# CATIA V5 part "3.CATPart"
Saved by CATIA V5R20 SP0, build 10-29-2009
Part number: 3
Bounding box of the stored display mesh (mm): x -65 to 65, y 0 to 180, z -0.347 to 44.383
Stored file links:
  E:\Ehsan\Amoozesh\CATIA\CATIA Course\Advanced\Videos\Session-18\3.CATPart
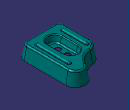
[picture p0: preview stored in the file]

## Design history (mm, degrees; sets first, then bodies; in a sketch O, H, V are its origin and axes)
Set1
  Sweep1: type Segment, GuideCrv Sketch7, GuideSurf xy-plane, Length1 40, Length2 0, Angle 80
  Boundary1: Boundary edge of Sweep1
  Fill1: Boundary Boundary1
  Sketch1 on Fill1, origin (0, 0, 39.3923), H (1, 0, 0), V (0, 1, 0)
    construction line L1 (0, 50) -> (0, 100)
    point P1 (0, 50)
    line L2 (-22.5, 50) -> (-22.5, 100)
    line L3 (22.5, 100) -> (22.5, 50)
    arc A1 centre (0, 100) radius 22.5 from (-22.5, 100) to (22.5, 100) cw
    arc A2 centre (0, 50) radius 22.5 from (22.5, 50) to (-22.5, 50) cw
    distance L1 L2 = 22.5
    length L1 = 50
    distance P1 H = 50
    coincidence: P1 V
    vertical: L1 V
    tangency: A1 L2, A2 L2, A1 L3, A2 L3
  Sweep2: type Segment, GuideCrv Sketch1, GuideSurf xy-plane, Length1 20, Length2 0, Angle 72.5
  Boundary2: Boundary edge of Sweep2
  Fill2: Boundary Boundary2
  Split1: ToCut Fill1, Cutting Sketch1
  Sketch2 on Fill2, origin (0, 0, 20.318), H (1, 0, 0), V (0, 1, 0)
    circle A1 centre (0, 90) radius 8
    point P1 (0, 90)
    circle A2 centre (0, 60) radius 8
    point P2 (0, 60)
    reference projected line E1 (22.5, 50) -> (16.4859, 50) from edge [face of Sweep2 | face of Sweep2]
    radius A1 = 8
    radius A2 = 8
    distance P2 P1 = 30
    distance P2 E1 = 10
    coincidence: P1 V, P2 V
  Split2: ToCut Fill2, Cutting Sketch2
  Plane1: type Offset, RefPlane zx-plane, Offset 35
  Sketch3 on Plane1, origin (0, 35, 0), H (-1, 0, 0), V (0, 0, 1)
    arc A1 centre (40, 39.3923) radius 5 from (45, 39.3923) to (35, 39.3923) ccw
    point P1 (40, 39.3923)
    reference projected line E1 (45, 39.3923) -> (-45, 39.3923) from edge of Sweep1
    construction line L1 (45, 39.3923) -> (35, 39.3923)
    point P2 (45, 39.3923)
    point P3 (35, 39.3923)
    point P4 (-35, 39.3923)
    point P5 (-45, 39.3923)
    arc A2 centre (-40, 39.3923) radius 5 from (-45, 39.3923) to (-35, 39.3923) cw
    construction line L2 (-45, 39.3923) -> (-35, 39.3923)
    point P7 (-45, 39.3923)
    axis line L3 (35, 39.3923) -> (45, 39.3923)
    radius A1 = 5
    distance P1 V = 40
    coincidence: P1 E1, P7 A2
    horizontal: L1 H, L2 H, L3 H
    symmetry: P3 P4 V, P2 P5 V, A1 A2 V
  Extrude1: Lim1 75, Lim2 0, Element1 Sketch3
  Extrude2: Lim1 100, Lim2 0, Direction edge of Fill1, Element1 sketch element
  Revol1: Element1 Sketch3, Angle1 0
  Line1: type PtPt, FirstPoint vertex of Sketch3, SecondPoint vertex of Sketch3
  Revol2: Element1 sketch element, Angle1 90, Line Line1
  Plane2: type Offset, RefPlane Plane1, Offset 100
  Sketch4 on Plane2, origin (0, 135, 0), H (-1, 0, 0), V (0, 0, 1)
    projected arc E1 centre (-40, 39.3923) radius 5 from (-35, 39.3923) to (-45, 39.3923) ccw from sketch element
    axis line L1 (-45, 39.3923) -> (-35, 39.3923)
    horizontal: L1 H
  Revol3: Element1 Sketch4, Angle1 90
  Plane3: type Offset, RefPlane Plane1, Offset 75
  Sketch5 on Plane3, origin (0, 110, 0), H (-1, 0, 0), V (0, 0, 1)
    projected arc E1 centre (40, 39.3923) radius 5 from (45, 39.3923) to (35, 39.3923) ccw from Sketch3.A1
    axis line L1 (35, 39.3923) -> (45, 39.3923)
    horizontal: L1 H
  Revol4: Element1 Sketch5, Angle1 90
  Sketch6 on Split1, origin (0, 0, 39.3923), H (1, 0, 0), V (0, 1, 0)
    projected line E1 (-45, 110) -> (-45, 35) from edge of Extrude1
    projected arc E2 centre (-40, 110) radius 5 from (-35, 110) to (-45, 110) ccw from edge of Revol4
    projected line E3 (-35, 35) -> (-35, 110) from edge of Extrude1
    projected arc E4 centre (-40, 35) radius 5 from (-45, 35) to (-35, 35) ccw from edge of Revol1
    projected arc E5 centre (40, 35) radius 5 from (35, 35) to (45, 35) ccw from edge of Revol2
    projected line E6 (35, 135) -> (35, 35) from edge of Extrude2
    projected line E7 (45, 35) -> (45, 135) from edge of Extrude2
    projected arc E8 centre (40, 135) radius 5 from (45, 135) to (35, 135) ccw from edge of Revol3
  Split3: ToCut Split1, Cutting Sketch6
  Join1: Elements (Split3; Sweep1; Sweep2; Extrude1; Extrude2; Revol1; Revol2; Revol3; Revol4; Split2)
  Fillet1: radius 5, on edge [face of Sweep1 | face of Fill1]; edge [face of Sweep2 | face of Fill2]
  Fillet2: radius 3, on edge [face of Sweep2 | face of Fill1]
  Fillet3: radius 1, on edge [face of Extrude2 | face of Fill1]; edge [face of Extrude1 from Sketch3.A1 | face of Fill1]
  ThickSurface1: Surface Fillet3, TopOffset 2, BotOffset 0
Body1 (main body)
  Sketch7 on xy-plane, origin (0, 0, 0), H (1, 0, 0), V (0, 1, 0)
    point P1 (-65, 0)
    line L1 (-65, 20) -> (-65, 100)
    point P2 (-65, 100)
    arc A1 centre (-29, 100) radius 36 from (-65, 100) to (-32.1861, 135.8587) cw
    arc A2 centre (-36.6113, 185.6625) radius 50 from (-32.1861, 135.8587) to (8.1457, 163.3734) ccw
    arc A3 centre (35, 150) radius 30 from (8.1457, 163.3734) to (65, 150) cw
    point P8 (65, 150)
    line L2 (65, 150) -> (65, 20)
    point P9 (65, 0)
    line L3 (-45, 0) -> (45, 0)
    point P10 (65, 0)
    arc A4 centre (45, 20) radius 20 from (65, 20) to (45, 0) cw
    arc A5 centre (-45, 20) radius 20 from (-65, 20) to (-45, 0) ccw
    radius A1 = 36
    radius A3 = 30
    radius A2 = 50
    distance P8 P9 = 150
    distance P1 P10 = 130
    radius A4 = 20
    distance P1 P2 = 100
    radius A5 = 20 {= Sketch7.radius(A4)}
    coincidence: P1 H, P9 H, P10 P9, L2 P9, L3 P10, L1 P1, L3 P1
    vertical: L1 V
    tangency: A1 L1, A2 A1, A3 A2, L2 A3, A4 L2, A4 L3, A5 L1, A5 L3
    horizontal: L3 H
    symmetry: L2 L1 V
